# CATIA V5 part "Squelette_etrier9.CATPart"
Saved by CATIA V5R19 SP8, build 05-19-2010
Part number: Squelette_etrier9
Bounding box of the stored display mesh (mm): x 10 to 30, y 20 to 20, z 10 to 50
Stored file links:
  G:\EU_thinkMotion\CFAO_2010\MMS_groupe2\MMS_groupe2\A reprendre\jcauchy\Squelette_etrier9.CATPart
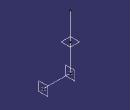
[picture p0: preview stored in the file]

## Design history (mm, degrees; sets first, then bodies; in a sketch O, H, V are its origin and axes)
Parameters
  Longueurfixation_etrier9 = 20 mm
  Longueurcorps_etrier9 = 40 mm
  Longueurcontacttige_etrier9 = 20 mm
Set1
  Point1: (10 {= 30mm-Longueurfixation_etrier9}, 20, 10)
  Point2: (30 {= 10mm+Longueurfixation_etrier9}, 20, 10)
  Line1: type PtPt, FirstPoint Point1, SecondPoint Point2
  Plane1: type Normal, Curve Line1, RefPoint Point1
  Plane2: type Normal, Curve Line1, RefPoint Point2
  Point3: type OnCurve, Support Line1, RefPoint Point2, Length -20 {= -Longueurfixation_etrier9}
  Line2: type Angle, RefPoint Point3, Curve Line1, Support zx-plane, Start 0, End -20 {= -Longueurcontacttige_etrier9}, Angle 90
  Plane3: type Normal, Curve Line2, RefPoint vertex of Line2
  Line3: type Normal, RefPoint vertex of Line2, RefSkin Plane3, Start 0, End -20 {= -Longueurcorps_etrier9 +Longueurcontacttige_etrier9}
Body1 (main body)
